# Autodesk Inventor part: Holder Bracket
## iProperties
Shininess: 50.0
Length Units: 11272
Angle Units: 11279
Time Units: 11290
Mass Units: 11286
Length Display Precision: 4
Angle Display Precision: 2
Compacted: True
Company: Autodesk
Manager: Lebovitz
Created: 2000-11
Part Number: Holder Bracket
Document SubType Name: Modeling
Designer: The PD Team
Project: Inventor Samples
Checked By: The PD Team
Density: 0.0
Volumn: 0.0
Area: 0.0
PropertySet Name: Model Information
Control State: 0
Master: False
Checked Out: False
Author: The PD Team
Revision Number: A
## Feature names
1. Revolution1
2. Extrusion1
3. Extrusion2
4. Extrusion3
5. Extrusion4
6. Extrusion5
7. Extrusion6
8. Fillet1
9. Extrusion7
10. Hole1
11. Hole2
12. Hole3
13. Hole4
14. Extrusion8
15. Hole5
16. Hole6
17. Hole7
18. Hole8
19. Fillet2
20. Fillet3
21. Fillet4
22. Fillet5
23. Fillet6
